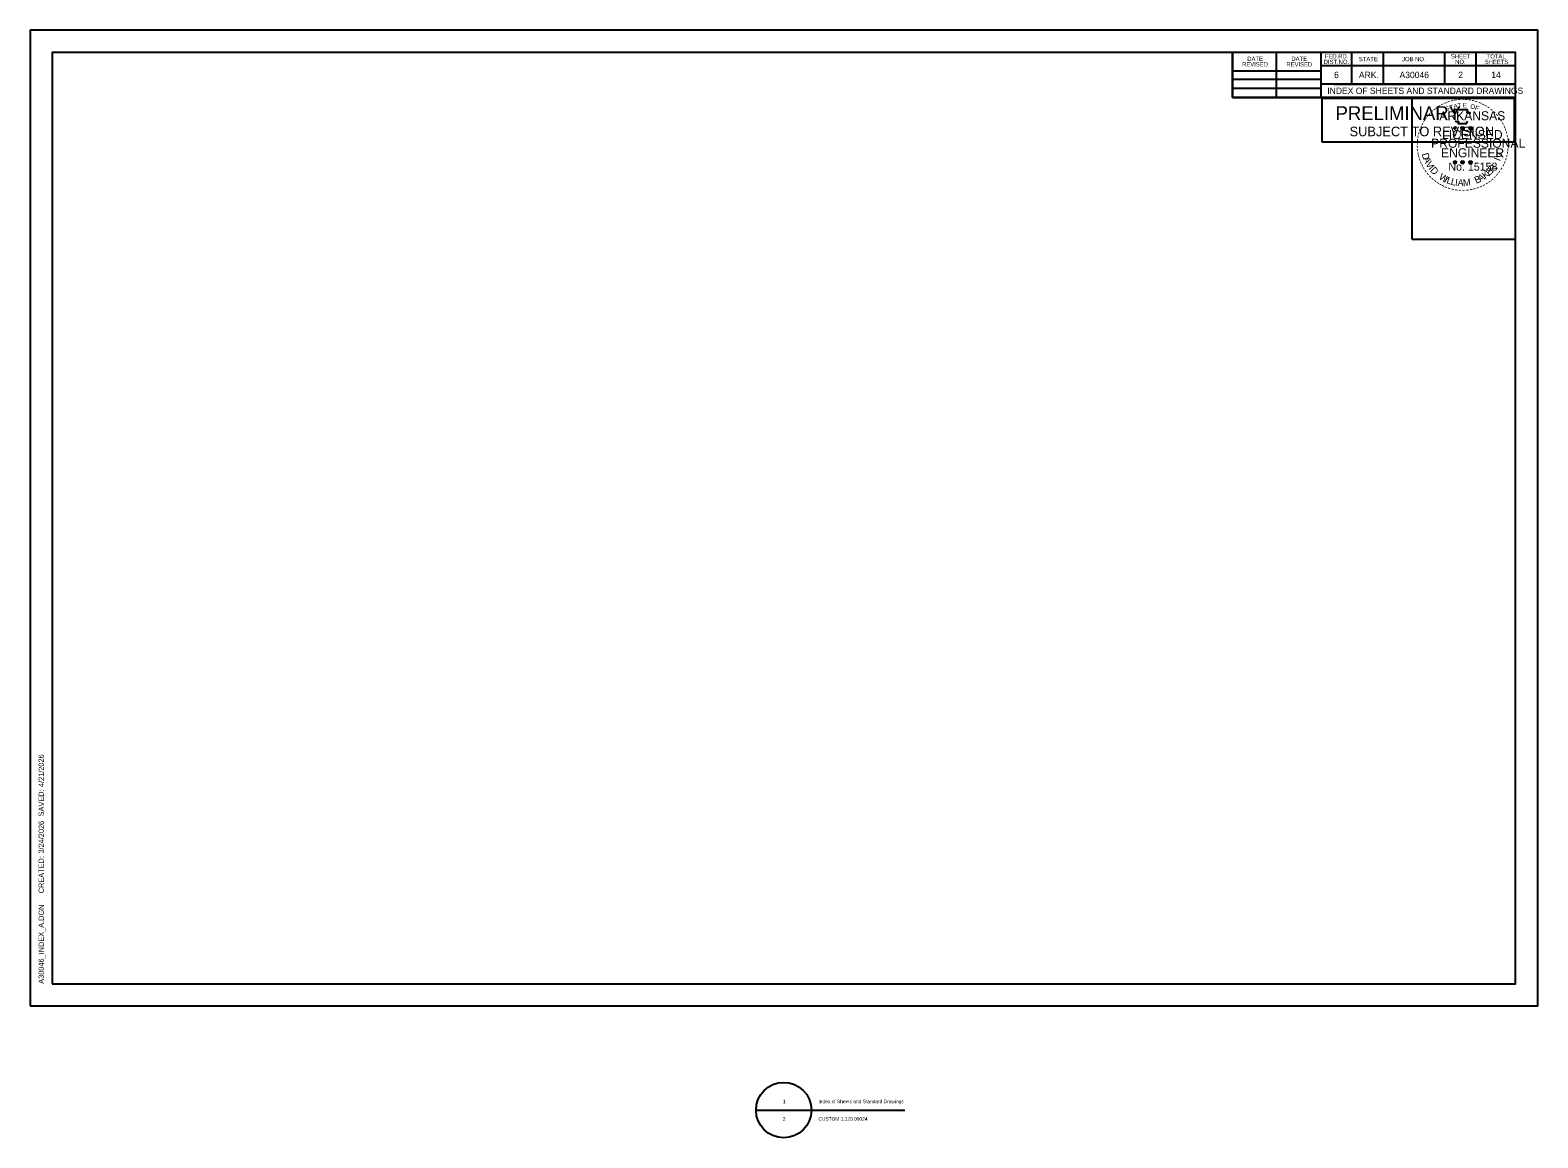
# Model space of a CAD drawing. Extents: x 0 to 1.42, y -0.12 to 0.92.
import ezdxf

# ---------------------------------------------------------------- set-up
doc = ezdxf.new("R2010")
doc.units = 0
for name, color, linetype in [('Default', 7, 'Continuous'), ('R_Border Notes', 7, 'Continuous'), ('R_Border PE', 7, 'Continuous'), ('SHET_Annotations', 7, 'Continuous'), ('SHET_Border-Lines', 7, 'Continuous'), ('SHET_Stamp-PE-Chief-Eng', 7, 'Continuous')]:
    doc.layers.add(name, color=color, linetype=linetype)

msp = doc.modelspace()

# ---------------------------------------------------------------- linework, layer by layer
at = {"layer": 'Default'}
for p, q in [((0.6821, -0.0979), (0.7341, -0.0979)), ((0.7083, -0.0979), (0.822, -0.0979))]:
    msp.add_line(p, q, dxfattribs=at)
msp.add_circle((0.7081, -0.0979), 0.026, dxfattribs=at)
at = {"layer": 'R_Border Notes'}
for p, q in [((0.1176, 0.8988), (0.1176, 0.8988)), ((0.1176, 0.8988), (0.1176, 0.8988)), ((1.1296, 0.8534), (1.1296, 0.8958)), ((1.1711, 0.8534), (1.1711, 0.8958)), ((1.2127, 0.8958), (1.2127, 0.8534)), ((1.2417, 0.8958), (1.2417, 0.866)), ((1.2712, 0.8958), (1.2712, 0.866)), ((1.3289, 0.8958), (1.3289, 0.866)), ((1.3584, 0.8958), (1.3584, 0.866)), ((1.1296, 0.8786), (1.2127, 0.8786)), ((1.3958, 0.8832), (1.2127, 0.8832)), ((1.3958, 0.8833), (1.3958, 0.8833)), ((1.1296, 0.8706), (1.2127, 0.8706)), ((1.3958, 0.866), (1.2127, 0.866)), ((1.2252, 0.866), (1.3958, 0.866)), ((1.1296, 0.8622), (1.2127, 0.8622)), ((1.3958, 0.8534), (1.1296, 0.8534))]:
    msp.add_line(p, q, dxfattribs=at)
for points in [[(0, 0), (1.4167, 0), (1.4167, 0.9167), (0, 0.9167)], [(0.0208, 0.0208), (1.3958, 0.0208), (1.3958, 0.8958), (0.0208, 0.8958)], [(1.1296, 0.8534), (1.3958, 0.8534), (1.3958, 0.8958), (1.1296, 0.8958)]]:
    msp.add_lwpolyline(points, close=True, dxfattribs=at)
at = {"layer": 'SHET_Annotations'}
msp.add_lwpolyline([(1.2137, 0.8119), (1.3948, 0.8119), (1.3948, 0.8524), (1.2137, 0.8524)], close=True, dxfattribs=at)
at = {"layer": 'SHET_Border-Lines'}
for p, q in [((1.3373, 0.8252), (1.3388, 0.8247)), ((1.3373, 0.8252), (1.3384, 0.825)), ((1.3373, 0.8252), (1.3383, 0.8247)), ((1.3379, 0.8235), (1.3388, 0.8247)), ((1.3379, 0.8235), (1.3384, 0.8245)), ((1.3379, 0.8235), (1.3388, 0.8244)), ((1.3388, 0.8263), (1.3386, 0.8252)), ((1.3388, 0.8247), (1.3388, 0.8263)), ((1.3388, 0.8263), (1.339, 0.8252)), ((1.3403, 0.8252), (1.3388, 0.8247)), ((1.3397, 0.8235), (1.3388, 0.8247)), ((1.3397, 0.8235), (1.3388, 0.8244)), ((1.3403, 0.8252), (1.3391, 0.825)), ((1.3397, 0.8235), (1.3391, 0.8247)), ((1.3403, 0.8252), (1.3394, 0.8248)), ((1.3444, 0.8252), (1.3459, 0.8247)), ((1.3444, 0.8252), (1.3455, 0.825)), ((1.3444, 0.8252), (1.3454, 0.8247)), ((1.345, 0.8235), (1.3459, 0.8247)), ((1.345, 0.8235), (1.3455, 0.8245)), ((1.345, 0.8235), (1.3459, 0.8244)), ((1.3459, 0.8263), (1.3457, 0.8252)), ((1.3459, 0.8247), (1.3459, 0.8263)), ((1.3459, 0.8263), (1.3461, 0.8252)), ((1.3474, 0.8252), (1.3459, 0.8247)), ((1.3468, 0.8235), (1.3459, 0.8247)), ((1.3468, 0.8235), (1.3459, 0.8244)), ((1.3474, 0.8252), (1.3462, 0.825)), ((1.3468, 0.8235), (1.3462, 0.8247)), ((1.3474, 0.8252), (1.3465, 0.8248)), ((1.3519, 0.8252), (1.3534, 0.8247)), ((1.3519, 0.8252), (1.353, 0.825)), ((1.3519, 0.8252), (1.3529, 0.8246)), ((1.3525, 0.8234), (1.3534, 0.8247)), ((1.3525, 0.8234), (1.353, 0.8245)), ((1.3525, 0.8234), (1.3534, 0.8243)), ((1.3534, 0.8262), (1.3532, 0.8252)), ((1.3534, 0.8247), (1.3534, 0.8262)), ((1.3534, 0.8262), (1.3536, 0.8252)), ((1.3549, 0.8252), (1.3534, 0.8247)), ((1.3543, 0.8234), (1.3534, 0.8247)), ((1.3543, 0.8234), (1.3534, 0.8243)), ((1.3549, 0.8252), (1.3537, 0.825)), ((1.3543, 0.8234), (1.3537, 0.8247)), ((1.3549, 0.8252), (1.354, 0.8247)), ((1.3388, 0.7941), (1.3386, 0.793)), ((1.3388, 0.7926), (1.3388, 0.7941)), ((1.3388, 0.7941), (1.339, 0.793)), ((1.3459, 0.7941), (1.3457, 0.793)), ((1.3459, 0.7926), (1.3459, 0.7941)), ((1.3459, 0.7941), (1.3461, 0.793)), ((1.3534, 0.7941), (1.3532, 0.793)), ((1.3534, 0.7925), (1.3534, 0.7941)), ((1.3534, 0.7941), (1.3536, 0.793)), ((1.3373, 0.793), (1.3388, 0.7926)), ((1.3373, 0.793), (1.3384, 0.7928)), ((1.3373, 0.793), (1.3383, 0.7925)), ((1.3379, 0.7913), (1.3388, 0.7926)), ((1.3379, 0.7913), (1.3384, 0.7923)), ((1.3379, 0.7913), (1.3388, 0.7922)), ((1.3403, 0.793), (1.3388, 0.7926)), ((1.3397, 0.7913), (1.3388, 0.7926)), ((1.3397, 0.7913), (1.3388, 0.7922)), ((1.3403, 0.793), (1.3391, 0.7928)), ((1.3397, 0.7913), (1.3391, 0.7925)), ((1.3403, 0.793), (1.3394, 0.7926)), ((1.3444, 0.793), (1.3459, 0.7926)), ((1.3444, 0.793), (1.3455, 0.7928)), ((1.3444, 0.793), (1.3454, 0.7925)), ((1.345, 0.7913), (1.3459, 0.7926)), ((1.345, 0.7913), (1.3455, 0.7923)), ((1.345, 0.7913), (1.3459, 0.7922)), ((1.3474, 0.793), (1.3459, 0.7926)), ((1.3468, 0.7913), (1.3459, 0.7926)), ((1.3468, 0.7913), (1.3459, 0.7922)), ((1.3474, 0.793), (1.3461, 0.7928)), ((1.3468, 0.7913), (1.3462, 0.7925)), ((1.3474, 0.793), (1.3465, 0.7926)), ((1.3519, 0.793), (1.3534, 0.7925)), ((1.3519, 0.793), (1.353, 0.7928)), ((1.3519, 0.793), (1.3529, 0.7925)), ((1.3525, 0.7912), (1.3534, 0.7925)), ((1.3525, 0.7912), (1.353, 0.7923)), ((1.3525, 0.7912), (1.3534, 0.7922)), ((1.3549, 0.793), (1.3534, 0.7925)), ((1.3543, 0.7912), (1.3534, 0.7925)), ((1.3543, 0.7912), (1.3534, 0.7922)), ((1.3549, 0.793), (1.3537, 0.7928)), ((1.3543, 0.7912), (1.3537, 0.7925)), ((1.3549, 0.793), (1.354, 0.7926))]:
    msp.add_line(p, q, dxfattribs=at)
msp.add_lwpolyline([(1.2983, 0.7203), (1.3958, 0.7203), (1.3958, 0.8534), (1.2983, 0.8534)], close=True, dxfattribs=at)
for points in [[(1.3375, 0.8417), (1.3386, 0.8382)], [(1.3524, 0.8378), (1.353, 0.839), (1.3501, 0.8389), (1.3507, 0.8417), (1.3375, 0.8417)], [(1.3396, 0.8314), (1.3396, 0.831), (1.342, 0.8309), (1.3418, 0.8289), (1.3497, 0.8289), (1.3506, 0.8312)], [(1.3459, 0.8263), (1.3468, 0.8235), (1.3444, 0.8252), (1.3474, 0.8252), (1.345, 0.8235), (1.3459, 0.8263)], [(1.3534, 0.8262), (1.3543, 0.8234), (1.3519, 0.8252), (1.3549, 0.8252), (1.3525, 0.8234), (1.3534, 0.8262)], [(1.3388, 0.7941), (1.3397, 0.7913), (1.3373, 0.793), (1.3403, 0.793), (1.3379, 0.7913), (1.3388, 0.7941)], [(1.3459, 0.7941), (1.3468, 0.7913), (1.3444, 0.793), (1.3474, 0.793), (1.345, 0.7913), (1.3459, 0.7941)], [(1.3534, 0.7941), (1.3543, 0.7912), (1.3519, 0.793), (1.3549, 0.793), (1.3525, 0.7912), (1.3534, 0.7941)]]:
    msp.add_lwpolyline(points, dxfattribs=at)
for centre, radius in [((1.3388, 0.8247), 0.000732), ((1.3388, 0.8247), 0.000614), ((1.3388, 0.8247), 0.000492), ((1.3388, 0.8247), 0.000421), ((1.3388, 0.8247), 0.000318), ((1.3388, 0.8247), 0.000211), ((1.3388, 0.8247), 0.000126), ((1.3459, 0.8247), 0.000732), ((1.3459, 0.8247), 0.000614), ((1.3459, 0.8247), 0.000492), ((1.3459, 0.8247), 0.000421), ((1.3459, 0.8247), 0.000318), ((1.3459, 0.8247), 0.000211), ((1.3459, 0.8247), 0.000126), ((1.3534, 0.8247), 0.000732), ((1.3534, 0.8247), 0.000614), ((1.3534, 0.8247), 0.000492), ((1.3534, 0.8247), 0.000421), ((1.3534, 0.8247), 0.000318), ((1.3534, 0.8247), 0.000211), ((1.3534, 0.8247), 0.000126), ((1.3388, 0.7926), 0.000732), ((1.3388, 0.7926), 0.000614), ((1.3388, 0.7926), 0.000492), ((1.3388, 0.7926), 0.000421), ((1.3388, 0.7926), 0.000318), ((1.3388, 0.7926), 0.000211), ((1.3388, 0.7926), 0.000126), ((1.3459, 0.7926), 0.000732), ((1.3459, 0.7926), 0.000614), ((1.3459, 0.7926), 0.000492), ((1.3459, 0.7926), 0.000421), ((1.3459, 0.7926), 0.000318), ((1.3459, 0.7926), 0.000211), ((1.3459, 0.7926), 0.000126), ((1.3534, 0.7925), 0.000732), ((1.3534, 0.7925), 0.000614), ((1.3534, 0.7925), 0.000492), ((1.3534, 0.7925), 0.000421), ((1.3534, 0.7925), 0.000318), ((1.3534, 0.7925), 0.000211), ((1.3534, 0.7925), 0.000126)]:
    msp.add_circle(centre, radius, dxfattribs=at)

# ---------------------------------------------------------------- texts
at = {"layer": 'Default'}
for s, height, p in [('1', 0.00328, (0.7073, -0.0914)), ('Index of Sheets and Standard Drawings', 0.003281, (0.7407, -0.0914)), ('2', 0.00328, (0.7072, -0.1078)), ('CUSTOM 1:120.00024', 0.003281, (0.7407, -0.1078))]:
    msp.add_text(s, height=height, dxfattribs=at).set_placement(p)
at = {"layer": 'R_Border PE'}
for s, p in [('6', (1.2252, 0.8716)), ('ARK.', (1.2485, 0.8716)), ('A30046', (1.2867, 0.8716)), ('2', (1.3419, 0.8716)), ('14', (1.3729, 0.8717)), ('INDEX OF SHEETS AND STANDARD DRAWINGS', (1.2188, 0.8567))]:
    msp.add_text(s, height=0.006, dxfattribs=at).set_placement(p)
at = {"layer": 'SHET_Annotations'}
for s, height, p in [('PRELIMINARY', 0.013, (1.2266, 0.8322)), ('SUBJECT TO REVISION', 0.009, (1.2398, 0.817))]:
    msp.add_text(s, height=height, dxfattribs=at).set_placement(p)
at = {"layer": 'SHET_Border-Lines'}
for s, height, rotation, p in [('-', 0.0068, 19.1761, (1.3322, 0.8465)), ('-', 0.0068, 13.6302, (1.3354, 0.8475)), ('-', 0.0068, 10.2193, (1.3383, 0.8482)), ('-', 0.0068, 5.8968, (1.3414, 0.8487)), ('-', 0.0068, 0.1862, (1.3446, 0.849)), ('-', 0.0068, 357.743, (1.3477, 0.8489)), ('-', 0.0068, 352.1617, (1.3509, 0.8487)), ('-', 0.0068, 347.2049, (1.3539, 0.8482)), ('-', 0.0068, 342.3362, (1.3566, 0.8475)), ('-', 0.0068, 50.6142, (1.3143, 0.8333)), ('-', 0.0068, 48.4231, (1.316, 0.8353)), ('-', 0.0068, 42.9622, (1.3179, 0.8374)), ('-', 0.0068, 38.9507, (1.3198, 0.8391)), ('-', 0.0068, 36.2317, (1.3218, 0.8407)), ('-', 0.0068, 34.0636, (1.3243, 0.8424)), ('-', 0.0068, 28.7918, (1.3268, 0.844)), ('-', 0.0068, 24.3072, (1.3295, 0.8453)), ('S', 0.00425, 21.594, (1.3305, 0.8403)), ('T', 0.00425, 16.4036, (1.3344, 0.8417)), ('A', 0.00425, 11.2132, (1.3379, 0.8428)), ('T', 0.00425, 6.0228, (1.3415, 0.8435)), ('E', 0.00425, 0.8323, (1.3462, 0.844)), ('O', 0.00425, 350.4515, (1.353, 0.8431)), ('F', 0.00425, 340.0707, (1.3571, 0.8421)), ('-', 0.0068, 337.8551, (1.3597, 0.8466)), ('-', 0.0068, 334.1211, (1.3624, 0.8454)), ('-', 0.0068, 329.6409, (1.3649, 0.8442)), ('-', 0.0068, 325.8627, (1.3676, 0.8427)), ('-', 0.0068, 320.5297, (1.3702, 0.8409)), ('-', 0.0068, 315.5786, (1.3728, 0.8388)), ('-', 0.0068, 309.8797, (1.3752, 0.8365)), ('-', 0.0068, 72.3945, (1.3078, 0.8207)), ('-', 0.0068, 67.7743, (1.3088, 0.8234)), ('-', 0.0068, 62.8713, (1.3099, 0.826)), ('-', 0.0068, 58.0706, (1.3112, 0.8286)), ('-', 0.0068, 54.2325, (1.3126, 0.8309)), ('-', 0.0068, 306.6522, (1.3774, 0.8339)), ('-', 0.00595, 303.6753, (1.3795, 0.8315)), ('-', 0.0068, 299.6684, (1.3808, 0.8289)), ('-', 0.0068, 294.6628, (1.3822, 0.8263)), ('-', 0.0068, 290.5728, (1.3833, 0.8239)), ('-', 0.0068, 285.1233, (1.3843, 0.8214)), ('-', 0.0068, 89.0622, (1.306, 0.8088)), ('-', 0.0068, 94.1959, (1.3061, 0.8057)), ('-', 0.0068, 85.1863, (1.3061, 0.8117)), ('-', 0.0068, 81.2013, (1.3064, 0.8147)), ('-', 0.0068, 75.461, (1.307, 0.8177)), ('-', 0.0068, 280.5493, (1.3851, 0.8182)), ('-', 0.0068, 276.5962, (1.3858, 0.815)), ('-', 0.0068, 274.3301, (1.3861, 0.8119)), ('-', 0.0068, 269.9407, (1.3862, 0.8092)), ('-', 0.0068, 98.9479, (1.3065, 0.8028)), ('-', 0.0068, 101.7149, (1.307, 0.7997)), ('-', 0.0068, 105.4578, (1.3077, 0.7972)), ('-', 0.0068, 109.0874, (1.3086, 0.7945)), ('-', 0.0068, 114.0643, (1.3097, 0.792)), ('D', 0.00654, 286.2848, (1.3074, 0.8003)), ('A', 0.00654, 292.7835, (1.3086, 0.796)), ('V', 0.00654, 300.7936, (1.3108, 0.791)), ('I', 0.00654, 69.0301, (1.3812, 0.7931)), ('V', 0.00654, 72.6573, (1.3822, 0.7954)), ('-', 0.0068, 247.8887, (1.3837, 0.7948)), ('-', 0.0068, 252.8681, (1.3846, 0.7977)), ('-', 0.0068, 255.7626, (1.3854, 0.8007)), ('-', 0.0068, 260.9953, (1.3858, 0.8036)), ('-', 0.0068, 263.5172, (1.3861, 0.8064)), ('-', 0.0068, 115.7289, (1.311, 0.7894)), ('-', 0.0068, 120.4471, (1.3125, 0.7869)), ('-', 0.0068, 125.8934, (1.3142, 0.7845)), ('-', 0.0068, 130.7181, (1.3162, 0.7821)), ('I', 0.00654, 308.3502, (1.3135, 0.7866)), ('-', 0.0068, 134.2238, (1.3184, 0.7798)), ('D', 0.00654, 311.9774, (1.315, 0.7847)), ('W', 0.00654, 328.0731, (1.323, 0.7771)), ('I', 0.00654, 336.6877, (1.328, 0.7741)), ('B', 0.00654, 22.8589, (1.3587, 0.7723)), ('A', 0.00654, 28.9042, (1.3625, 0.7739)), ('K', 0.00654, 36.9143, (1.3672, 0.7766)), ('E', 0.00654, 44.0175, (1.3711, 0.7795)), ('R', 0.00654, 50.3651, (1.3742, 0.7825)), ('-', 0.0068, 225.7653, (1.3753, 0.7814)), (',', 0.00654, 57.4684, (1.3773, 0.7863)), ('-', 0.0068, 231.2538, (1.3773, 0.7838)), ('-', 0.0068, 233.8452, (1.3792, 0.7862)), ('-', 0.0068, 239.0712, (1.3809, 0.789)), ('-', 0.0068, 244.6197, (1.3825, 0.7921)), ('-', 0.0068, 138.9338, (1.3206, 0.7778)), ('-', 0.0068, 144.6463, (1.323, 0.7761)), ('-', 0.0068, 148.0898, (1.3254, 0.7745)), ('-', 0.0068, 151.5704, (1.3278, 0.7732)), ('-', 0.0068, 154.6002, (1.3301, 0.7721)), ('-', 0.0068, 158.5612, (1.3327, 0.771)), ('L', 0.00654, 340.3149, (1.3303, 0.7731)), ('-', 0.0068, 162.7983, (1.3356, 0.7701)), ('L', 0.00654, 346.6625, (1.3344, 0.7716)), ('-', 0.0068, 167.5555, (1.3387, 0.7694)), ('-', 0.0068, 173.1155, (1.3419, 0.769)), ('I', 0.00654, 353.0101, (1.3386, 0.7706)), ('A', 0.00654, 356.6373, (1.341, 0.7703)), ('-', 0.0068, 176.5183, (1.3451, 0.7687)), ('-', 0.0068, 181.5918, (1.3483, 0.7688)), ('M', 0.00654, 4.6473, (1.3465, 0.77)), ('-', 0.0068, 185.8167, (1.3517, 0.7691)), ('-', 0.0068, 191.2858, (1.3549, 0.7697)), ('-', 0.0068, 195.4743, (1.358, 0.7705)), ('-', 0.0068, 199.4643, (1.3608, 0.7716)), ('-', 0.0068, 204.2516, (1.3635, 0.7727)), ('-', 0.0068, 207.3568, (1.3661, 0.7741)), ('-', 0.0068, 212.2491, (1.3685, 0.7756)), ('-', 0.0068, 215.7363, (1.3708, 0.7772)), ('-', 0.0068, 221.0851, (1.3731, 0.7792))]:
    msp.add_text(s, height=height, rotation=rotation, dxfattribs=at).set_placement(p)
for s, height, p in [('ARKANSAS', 0.0085, (1.3241, 0.832)), ('LICENSED', 0.0085, (1.3267, 0.8143)), ('PROFESSIONAL', 0.0085, (1.3164, 0.8062)), ('ENGINEER', 0.0085, (1.3257, 0.7972)), ('No. 15158', 0.00747, (1.3326, 0.7847)), ('AAMU', 0.000000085, (1.3456, 0.77))]:
    msp.add_text(s, height=height, dxfattribs=at).set_placement(p)
at = {"layer": 'SHET_Stamp-PE-Chief-Eng'}
for s, p in [('FED.RD.', (1.2165, 0.8901)), ('SHEET', (1.335, 0.8901)), ('TOTAL', (1.3686, 0.8901)), ('REVISED', (1.1388, 0.8826)), ('DATE', (1.1436, 0.8878)), ('REVISED', (1.1804, 0.8826)), ('DATE', (1.1851, 0.8878)), ('DIST.NO.', (1.2154, 0.8849)), ('STATE', (1.2485, 0.8875)), ('JOB NO.', (1.2891, 0.8875)), ('NO.', (1.339, 0.8849)), ('SHEETS', (1.3668, 0.8849))]:
    msp.add_text(s, height=0.004, dxfattribs=at).set_placement(p)
for s, p in [('4/21/2026', (0.0129, 0.2056)), ('  SAVED: ', (0.0129, 0.1742)), ('3/24/2026', (0.0129, 0.1431)), ('     CREATED: ', (0.0129, 0.0962)), ('A30046_INDEX_A.DGN', (0.0129, 0.0208))]:
    msp.add_text(s, height=0.005, rotation=90, dxfattribs=at).set_placement(p)

doc.saveas('drawing.dxf')
